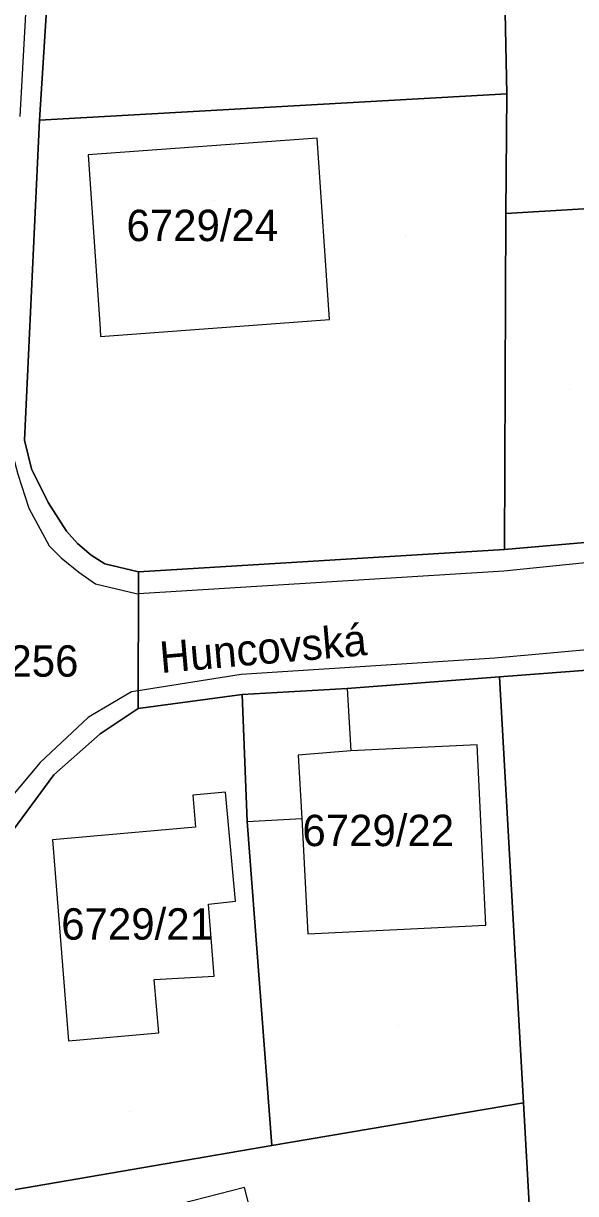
# Model space of a CAD drawing. Extents: x -266199 to -261993, y -1239047 to -1235108.
# Drawn here: x -264005.4 to -263970.2, y -1236261.5 to -1236187 of the extents above; entities that cross this region are included whole.
import ezdxf

# ---------------------------------------------------------------- set-up
doc = ezdxf.new("R2010")
doc.units = 0
for name, color, linetype in [('body_kn', 7, 'Continuous'), ('kladpar_druhypozemkov', 7, 'Continuous'), ('kladpar_hranice', 7, 'Continuous'), ('kladpar_parcelnecisla', 7, 'Continuous'), ('kladpar_plochy', 7, 'Continuous'), ('popisy', 7, 'Continuous'), ('zappar_hrandruhpozemk', 7, 'Continuous')]:
    doc.layers.add(name, color=color, linetype=linetype)

msp = doc.modelspace()

# ---------------------------------------------------------------- linework, layer by layer
at = {"layer": 'body_kn'}
for p, q in [((-263974.58, -1236191.46), (-263974.58, -1236191.46)), ((-264004.38, -1236193.13), (-264004.38, -1236193.13)), ((-264004.38, -1236193.13), (-264004.38, -1236193.13)), ((-263986.68, -1236194.27), (-263986.68, -1236194.27)), ((-264001.27, -1236195.35), (-264001.27, -1236195.35)), ((-263974.65, -1236199.08), (-263974.65, -1236199.08)), ((-263985.88, -1236205.84), (-263985.88, -1236205.84)), ((-263985.88, -1236205.84), (-263985.88, -1236205.84)), ((-264000.51, -1236206.44), (-264000.51, -1236206.44)), ((-264000.48, -1236206.92), (-264000.48, -1236206.92)), ((-264005.32, -1236213.52), (-264005.32, -1236213.52)), ((-264004.88, -1236215.35), (-264004.88, -1236215.35)), ((-264005.05, -1236217.86), (-264005.05, -1236217.86)), ((-264003.83, -1236217.5), (-264003.83, -1236217.5)), ((-264002.66, -1236219.32), (-264002.66, -1236219.32)), ((-264001.95, -1236220.12), (-264001.95, -1236220.12)), ((-264003.76, -1236220.26), (-264003.76, -1236220.26)), ((-264001.07, -1236220.85), (-264001.07, -1236220.85)), ((-263974.74, -1236220.5), (-263974.74, -1236220.5)), ((-263974.74, -1236220.5), (-263974.74, -1236220.5)), ((-264002.99, -1236221.03), (-264002.99, -1236221.03)), ((-264000.2, -1236221.41), (-264000.2, -1236221.41)), ((-264001.87, -1236221.93), (-264001.87, -1236221.93)), ((-263998.06, -1236221.91), (-263998.06, -1236221.91)), ((-263974.77, -1236221.88), (-263974.77, -1236221.88)), ((-264000.8, -1236222.68), (-264000.8, -1236222.68)), ((-263998.22, -1236223.29), (-263998.22, -1236223.29)), ((-263998.06, -1236223.33), (-263998.06, -1236223.33)), ((-263975.34, -1236227.42), (-263975.34, -1236227.42)), ((-263991.52, -1236228.47), (-263991.52, -1236228.47)), ((-263975.06, -1236228.6), (-263975.06, -1236228.6)), ((-263975.06, -1236228.6), (-263975.06, -1236228.6)), ((-263998.5, -1236229.57), (-263998.5, -1236229.57)), ((-263998.08, -1236229.5), (-263998.08, -1236229.5)), ((-263998.08, -1236229.5), (-263998.08, -1236229.5)), ((-263991.46, -1236229.73), (-263991.46, -1236229.73)), ((-263991.46, -1236229.73), (-263991.46, -1236229.73)), ((-263984.76, -1236229.36), (-263984.76, -1236229.36)), ((-263984.76, -1236229.36), (-263984.76, -1236229.36)), ((-263998.08, -1236230.62), (-263998.08, -1236230.62)), ((-263998.08, -1236230.62), (-263998.08, -1236230.62)), ((-264001.27, -1236231.2), (-264001.27, -1236231.2)), ((-264001.11, -1236231.1), (-264001.11, -1236231.1)), ((-264000.5, -1236232.25), (-264000.5, -1236232.25)), ((-263984.52, -1236233.32), (-263984.52, -1236233.32)), ((-263984.52, -1236233.32), (-263984.52, -1236233.32)), ((-263976.48, -1236232.94), (-263976.48, -1236232.94)), ((-264004.33, -1236234.08), (-264004.33, -1236234.08)), ((-263987.88, -1236233.61), (-263987.88, -1236233.61)), ((-264003.46, -1236234.86), (-264003.46, -1236234.86)), ((-263994.6, -1236236.15), (-263994.6, -1236236.15)), ((-263992.52, -1236235.96), (-263992.52, -1236235.96)), ((-263991.13, -1236237.82), (-263991.13, -1236237.82)), ((-263991.13, -1236237.82), (-263991.13, -1236237.82)), ((-263987.66, -1236237.64), (-263987.66, -1236237.64)), ((-263994.42, -1236238.2), (-263994.42, -1236238.2)), ((-264003.54, -1236239), (-264003.54, -1236239)), ((-263993.61, -1236243.09), (-263993.61, -1236243.09)), ((-263991.87, -1236242.9), (-263991.87, -1236242.9)), ((-263975.92, -1236244.43), (-263975.92, -1236244.43)), ((-263987.27, -1236244.98), (-263987.27, -1236244.98)), ((-263987.27, -1236244.98), (-263987.27, -1236244.98)), ((-263993.24, -1236247.68), (-263993.24, -1236247.68)), ((-263997.06, -1236247.91), (-263997.06, -1236247.91)), ((-263996.76, -1236251.3), (-263996.76, -1236251.3)), ((-264002.52, -1236251.81), (-264002.52, -1236251.81)), ((-264002.52, -1236251.81), (-264002.52, -1236251.81)), ((-263973.52, -1236255.75), (-263973.52, -1236255.75)), ((-263989.57, -1236258.49), (-263989.57, -1236258.49)), ((-263991.3, -1236261.16), (-263991.3, -1236261.16))]:
    msp.add_line(p, q, dxfattribs=at)
at = {"layer": 'kladpar_druhypozemkov'}
for p, q in [((-263993.19, -1236198.24), (-263993.19, -1236198.24)), ((-263981.04, -1236200.53), (-263981.04, -1236200.53)), ((-263970.6, -1236210.29), (-263970.6, -1236210.29)), ((-263982.35, -1236237.18), (-263982.35, -1236237.18)), ((-263998.49, -1236243.21), (-263998.49, -1236243.21)), ((-263981.52, -1236250.8), (-263981.52, -1236250.8)), ((-263998.66, -1236256.3), (-263998.66, -1236256.3))]:
    msp.add_line(p, q, dxfattribs=at)
at = {"layer": 'kladpar_hranice'}
for points in [[(-264004.38, -1236193.13), (-264002.46, -1236163.09), (-263975.01, -1236160.51), (-263974.95, -1236173.84), (-263974.58, -1236191.46), (-264004.38, -1236193.13)], [(-264002.46, -1236163.09), (-264004.38, -1236193.13), (-264005.32, -1236213.52), (-264004.88, -1236215.35), (-264003.83, -1236217.5), (-264002.66, -1236219.32), (-264001.95, -1236220.12), (-264001.07, -1236220.85), (-264000.2, -1236221.41), (-263998.06, -1236221.91), (-263998.06, -1236223.33), (-263998.08, -1236229.5), (-263998.08, -1236230.62), (-264000.5, -1236232.25), (-264003.46, -1236234.86), (-264006.61, -1236239.13)], [(-263998.08, -1236230.62), (-263998.08, -1236229.5), (-263998.06, -1236223.33), (-263998.06, -1236221.91), (-263974.74, -1236220.5), (-263958.14, -1236219.06), (-263956.09, -1236218.2), (-263953.81, -1236216.85), (-263952.84, -1236216), (-263951.19, -1236214.19), (-263949.73, -1236212.2), (-263949.22, -1236211.12), (-263949.07, -1236206.18), (-263949.46, -1236197.58), (-263950.24, -1236172.84)], [(-263974.95, -1236173.84), (-263950.24, -1236172.84), (-263949.46, -1236197.58), (-263974.65, -1236199.08), (-263974.58, -1236191.46), (-263974.95, -1236173.84)], [(-263974.74, -1236220.5), (-263998.06, -1236221.91), (-264000.2, -1236221.41), (-264001.07, -1236220.85), (-264001.95, -1236220.12), (-264002.66, -1236219.32), (-264003.83, -1236217.5), (-264004.88, -1236215.35), (-264005.32, -1236213.52), (-264004.38, -1236193.13), (-263974.58, -1236191.46), (-263974.65, -1236199.08), (-263974.74, -1236220.5)], [(-263974.74, -1236220.5), (-263974.65, -1236199.08), (-263949.46, -1236197.58), (-263949.07, -1236206.18), (-263949.22, -1236211.12), (-263949.73, -1236212.2), (-263951.19, -1236214.19), (-263952.84, -1236216), (-263953.81, -1236216.85), (-263956.09, -1236218.2), (-263958.14, -1236219.06), (-263974.74, -1236220.5)], [(-263909.64, -1236227.97), (-263933.05, -1236225.73), (-263936.6, -1236225.95), (-263943.67, -1236226.4), (-263956.86, -1236227.23), (-263975.06, -1236228.6), (-263984.76, -1236229.36), (-263991.46, -1236229.73), (-263998.08, -1236230.62)], [(-263975.06, -1236228.6), (-263956.86, -1236227.23), (-263954.42, -1236260.88)], [(-263991.46, -1236229.73), (-263984.76, -1236229.36), (-263975.06, -1236228.6), (-263973.52, -1236255.75), (-263989.57, -1236258.49), (-263991.13, -1236237.82), (-263991.46, -1236229.73)], [(-263972.72, -1236270.21), (-263973.52, -1236255.75), (-263975.06, -1236228.6)], [(-264007.4, -1236261.54), (-264007.56, -1236252.12), (-264007.15, -1236242.73), (-264006.61, -1236239.13), (-264003.46, -1236234.86), (-264000.5, -1236232.25), (-263998.08, -1236230.62), (-263991.46, -1236229.73), (-263991.13, -1236237.82), (-263989.57, -1236258.49), (-264007.4, -1236261.54)], [(-264004.83, -1236279.14), (-264006.37, -1236272.43), (-264007.4, -1236261.54), (-263989.57, -1236258.49), (-263973.52, -1236255.75), (-263972.72, -1236270.21), (-264004.83, -1236279.14)]]:
    msp.add_lwpolyline(points, dxfattribs=at)
at = {"layer": 'kladpar_plochy'}
for points in [[(-264004.38, -1236193.13), (-264002.46, -1236163.09), (-263975.01, -1236160.51), (-263974.95, -1236173.84), (-263974.58, -1236191.46)], [(-263974.95, -1236173.84), (-263950.24, -1236172.84), (-263949.46, -1236197.58), (-263974.65, -1236199.08), (-263974.58, -1236191.46)], [(-263974.74, -1236220.5), (-263998.06, -1236221.91), (-264000.2, -1236221.41), (-264001.07, -1236220.85), (-264001.95, -1236220.12), (-264002.66, -1236219.32), (-264003.83, -1236217.5), (-264004.88, -1236215.35), (-264005.32, -1236213.52), (-264004.38, -1236193.13), (-263974.58, -1236191.46), (-263974.65, -1236199.08)], [(-263974.74, -1236220.5), (-263974.65, -1236199.08), (-263949.46, -1236197.58), (-263949.07, -1236206.18), (-263949.22, -1236211.12), (-263949.73, -1236212.2), (-263951.19, -1236214.19), (-263952.84, -1236216), (-263953.81, -1236216.85), (-263956.09, -1236218.2), (-263958.14, -1236219.06)], [(-263975.06, -1236228.6), (-263956.86, -1236227.23), (-263954.42, -1236260.88), (-263955.66, -1236261.33), (-263963.32, -1236265.85), (-263970.63, -1236266.23), (-263970.47, -1236269.48), (-263969.36, -1236269.42), (-263969.55, -1236269.53), (-263972.72, -1236270.21), (-263973.52, -1236255.75)], [(-263991.46, -1236229.73), (-263984.76, -1236229.36), (-263975.06, -1236228.6), (-263973.52, -1236255.75), (-263989.57, -1236258.49), (-263991.13, -1236237.82)], [(-264007.4, -1236261.54), (-264007.56, -1236252.12), (-264007.15, -1236242.73), (-264006.61, -1236239.13), (-264003.46, -1236234.86), (-264000.5, -1236232.25), (-263998.08, -1236230.62), (-263991.46, -1236229.73), (-263991.13, -1236237.82), (-263989.57, -1236258.49)], [(-264004.83, -1236279.14), (-264006.37, -1236272.43), (-264007.4, -1236261.54), (-263989.57, -1236258.49), (-263973.52, -1236255.75), (-263972.72, -1236270.21)]]:
    msp.add_lwpolyline(points, close=True, dxfattribs=at)
for points in [[(-264002.46, -1236163.09), (-264004.38, -1236193.13), (-264005.32, -1236213.52), (-264004.88, -1236215.35), (-264003.83, -1236217.5), (-264002.66, -1236219.32), (-264001.95, -1236220.12), (-264001.07, -1236220.85), (-264000.2, -1236221.41), (-263998.06, -1236221.91), (-263998.06, -1236223.33), (-263998.08, -1236229.5), (-263998.08, -1236230.62), (-264000.5, -1236232.25), (-264003.46, -1236234.86), (-264006.61, -1236239.13)], [(-263956.86, -1236227.23), (-263975.06, -1236228.6), (-263984.76, -1236229.36), (-263991.46, -1236229.73), (-263998.08, -1236230.62), (-263998.08, -1236229.5), (-263998.06, -1236223.33), (-263998.06, -1236221.91), (-263974.74, -1236220.5), (-263958.14, -1236219.06)]]:
    msp.add_lwpolyline(points, dxfattribs=at)
at = {"layer": 'zappar_hrandruhpozemk'}
for p, q in [((-263986.68, -1236194.27), (-264001.27, -1236195.35)), ((-263985.88, -1236205.84), (-263986.68, -1236194.27)), ((-263957.59, -1236220.11), (-263974.77, -1236221.88)), ((-263974.77, -1236221.88), (-263998.06, -1236223.33)), ((-263959.24, -1236225.96), (-263975.34, -1236227.42)), ((-263984.76, -1236229.36), (-263984.52, -1236233.32)), ((-263984.52, -1236233.32), (-263987.88, -1236233.61)), ((-263991.13, -1236237.82), (-263987.66, -1236237.64)), ((-264003.54, -1236239), (-264002.52, -1236251.81)), ((-263987.27, -1236244.98), (-263975.92, -1236244.43)), ((-263988.51, -1236272.09), (-263991.3, -1236261.16))]:
    msp.add_line(p, q, dxfattribs=at)
for points in [[(-264000.38, -1236129.83), (-264002.72, -1236146.14), (-264003.96, -1236162.83), (-264005.62, -1236192.9)], [(-264001.27, -1236195.35), (-264000.51, -1236206.44), (-264000.48, -1236206.92), (-263985.88, -1236205.84)], [(-264006.3, -1236213.59), (-264005.75, -1236215.7), (-264005.05, -1236217.86), (-264003.76, -1236220.26), (-264002.99, -1236221.03), (-264001.87, -1236221.93), (-264000.8, -1236222.68), (-263998.22, -1236223.29), (-263998.06, -1236223.33)], [(-263975.34, -1236227.42), (-263991.52, -1236228.47), (-263998.08, -1236229.5)], [(-263998.08, -1236229.5), (-263998.5, -1236229.57), (-264001.11, -1236231.1), (-264001.27, -1236231.2), (-264004.33, -1236234.08), (-264006.3, -1236236.42), (-264007.8, -1236238.58)], [(-263975.92, -1236244.43), (-263976.48, -1236232.94), (-263984.52, -1236233.32)], [(-263987.88, -1236233.61), (-263987.66, -1236237.64), (-263987.27, -1236244.98)], [(-264002.52, -1236251.81), (-263996.76, -1236251.3), (-263997.06, -1236247.91), (-263993.24, -1236247.68), (-263993.61, -1236243.09), (-263991.87, -1236242.9), (-263992.52, -1236235.96), (-263994.6, -1236236.15), (-263994.42, -1236238.2), (-264003.54, -1236239)], [(-263991.3, -1236261.16), (-264001.26, -1236263.7), (-264000, -1236268.63), (-264001.33, -1236268.9), (-263999.86, -1236274.99), (-263988.51, -1236272.09)]]:
    msp.add_lwpolyline(points, dxfattribs=at)

# ---------------------------------------------------------------- texts
at = {"layer": 'kladpar_parcelnecisla'}
for s, p in [('6729/24', (-263998.827, -1236200.84)), ('6224/256', (-264013.047, -1236228.6)), ('6729/22', (-263987.614, -1236239.4)), ('6729/21', (-264002.987, -1236245.36))]:
    msp.add_text(s, height=2, dxfattribs=at).set_placement(p)
at = {"layer": 'popisy'}
msp.add_text('Huncovská', height=2, rotation=5, dxfattribs=at).set_placement((-263996.626, -1236228.371))

doc.saveas('drawing.dxf')
